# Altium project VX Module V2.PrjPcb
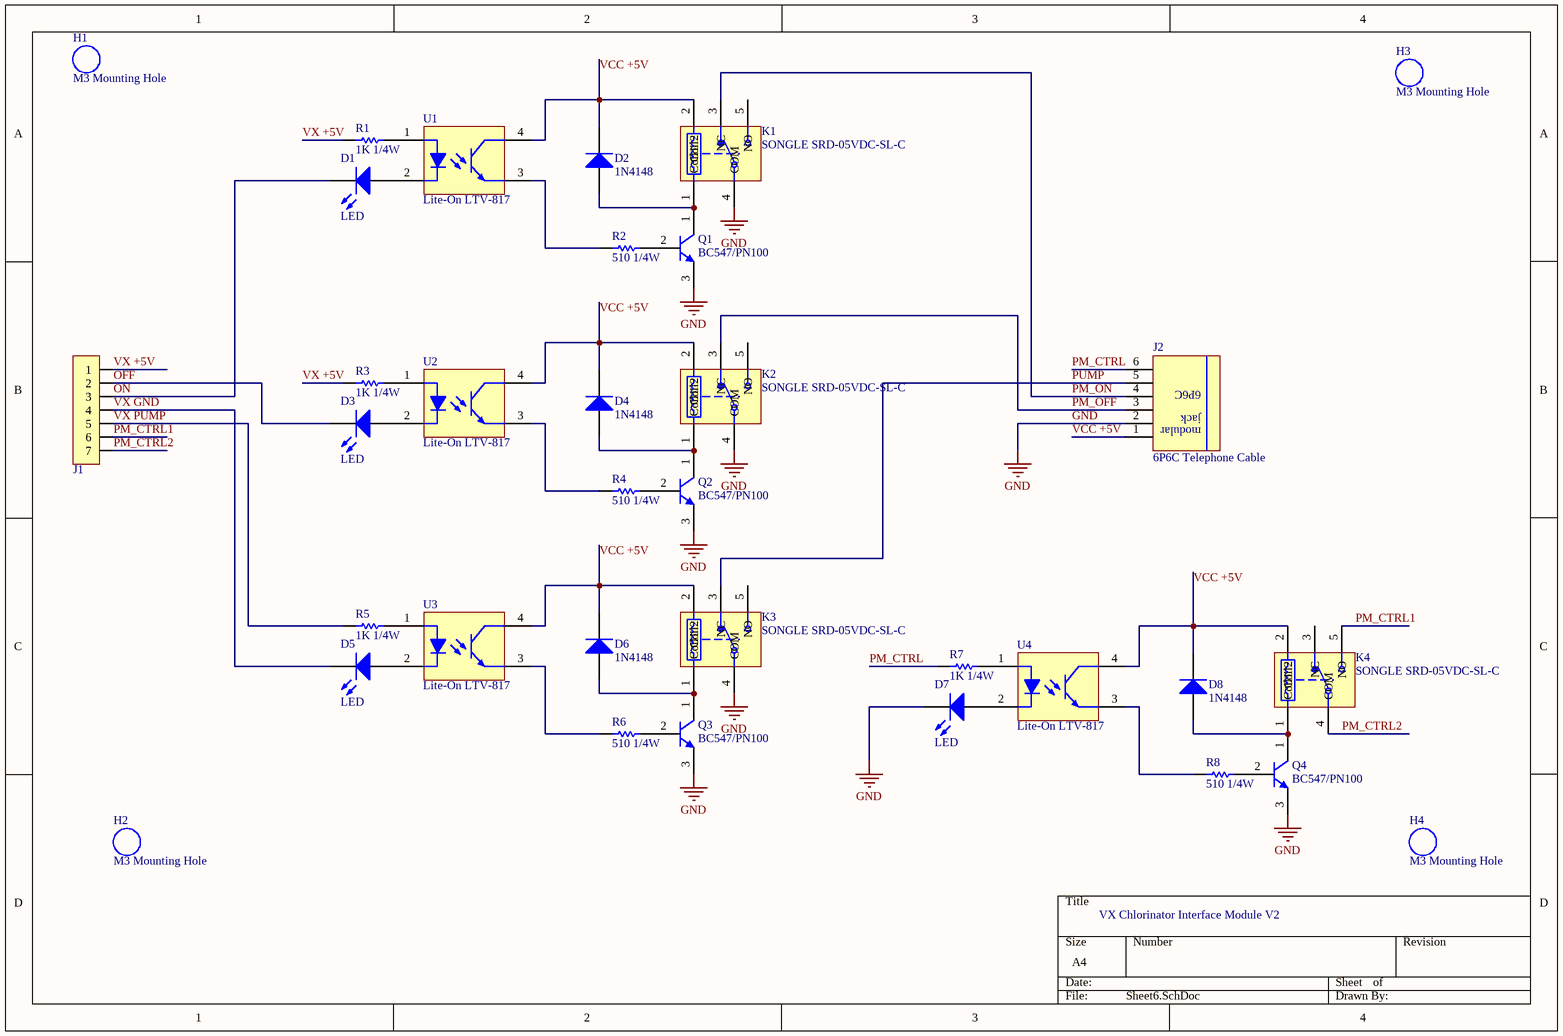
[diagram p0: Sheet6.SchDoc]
1 sheet, 34 parts. Net scope: global (net labels, ports and power ports of the same name join across sheets).

## Sheet Sheet6.SchDoc
size A4

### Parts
D1  LED  [PCB-6hmn14p3euwrtpae4j9f-1]
D2  1N4148  [PCB-rs5tsfd40ie4dftnk2d5-1]
D3  LED  [PCB-6hmn14p3euwrtpae4j9f-1]
D4  1N4148  [PCB-rs5tsfd40ie4dftnk2d5-1]
D5  LED  [PCB-6hmn14p3euwrtpae4j9f-1]
D6  1N4148  [PCB-rs5tsfd40ie4dftnk2d5-1]
D7  LED  [PCB-6hmn14p3euwrtpae4j9f-1]
D8  1N4148  [PCB-rs5tsfd40ie4dftnk2d5-1]
H1  M3 Mounting Hole  [PCB-sb9r54v1ukudlsmquqqd-1]
H2  M3 Mounting Hole  [PCB-sb9r54v1ukudlsmquqqd-1]
H3  M3 Mounting Hole  [PCB-sb9r54v1ukudlsmquqqd-1]
H4  M3 Mounting Hole  [PCB-sb9r54v1ukudlsmquqqd-1]
J1  7pin header  [PCBComponent_1 - duplicate]  (value not drawn)
J2  6P6C Telephone Cable  [PCB-617631-1]
K1  SONGLE SRD-05VDC-SL-C  [PCB-g2fdo3sb6id1q29ao90z-1]
K2  SONGLE SRD-05VDC-SL-C  [PCB-g2fdo3sb6id1q29ao90z-1]
K3  SONGLE SRD-05VDC-SL-C  [PCB-g2fdo3sb6id1q29ao90z-1]
K4  SONGLE SRD-05VDC-SL-C  [PCB-g2fdo3sb6id1q29ao90z-1]
Q1  BC547/PN100  [ONSC-TO-92-3-29-11_AM_BL]
Q2  BC547/PN100  [ONSC-TO-92-3-29-11_AM_BL]
Q3  BC547/PN100  [ONSC-TO-92-3-29-11_AM_BL]
Q4  BC547/PN100  [ONSC-TO-92-3-29-11_AM_BL]
R1  1K 1/4W  [PCB-b0svi7yxgb64se8nuirk-1]
R2  510 1/4W  [PCB-b0svi7yxgb64se8nuirk-1]
R3  1K 1/4W  [PCB-b0svi7yxgb64se8nuirk-1]
R4  510 1/4W  [PCB-b0svi7yxgb64se8nuirk-1]
R5  1K 1/4W  [PCB-b0svi7yxgb64se8nuirk-1]
R6  510 1/4W  [PCB-b0svi7yxgb64se8nuirk-1]
R7  1K 1/4W  [PCB-b0svi7yxgb64se8nuirk-1]
R8  510 1/4W  [PCB-b0svi7yxgb64se8nuirk-1]
U1  Lite-On LTV-817  [PCBComponent_1 - duplicate]
U2  Lite-On LTV-817  [PCBComponent_1 - duplicate]
U3  Lite-On LTV-817  [PCBComponent_1 - duplicate]
U4  Lite-On LTV-817  [PCBComponent_1 - duplicate]

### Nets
GND: D7.2(K) J2.2 K1.4(COM) K2.4(COM) K3.4(COM) Q1.3(E) Q2.3(E) Q3.3(E) Q4.3(E)
OFF: D3.2(K) J1.2
ON: D1.2(K) J1.3
PM_CTRL: J2.6 R7.2
PM_CTRL1: J1.6 K4.5(NO)
PM_CTRL2: J1.7 K4.4(COM)
PM_OFF: J2.3 K2.3(NC)
PM_ON: J2.4 K1.3(NC)
PUMP: J2.5 K3.3(NC)
VCC +5V: D2.2(K) D4.2(K) D6.2(K) D8.2(K) J2.1 K1.2(Coil2) K2.2(Coil2) K3.2(Coil2) K4.2(Coil2) U1.4(C) U2.4(C) U3.4(C) U4.4(C)
VX +5V: J1.1 R1.2 R3.2
VX GND: D5.2(K) J1.4
VX PUMP: J1.5 R5.2
NetD1_1: D1.1(A) U1.2(C)
NetD2_1: D2.1(A) K1.1(Coil1) Q1.1(C)
NetD3_1: D3.1(A) U2.2(C)
NetD4_1: D4.1(A) K2.1(Coil1) Q2.1(C)
NetD5_1: D5.1(A) U3.2(C)
NetD6_1: D6.1(A) K3.1(Coil1) Q3.1(C)
NetD7_1: D7.1(A) U4.2(C)
NetD8_1: D8.1(A) K4.1(Coil1) Q4.1(C)
NetQ1_2: Q1.2(B) R2.2
NetQ2_2: Q2.2(B) R4.2
NetQ3_2: Q3.2(B) R6.2
NetQ4_2: Q4.2(B) R8.2
NetR1_1: R1.1 U1.1(A)
NetR2_1: R2.1 U1.3(E)
NetR3_1: R3.1 U2.1(A)
NetR4_1: R4.1 U2.3(E)
NetR5_1: R5.1 U3.1(A)
NetR6_1: R6.1 U3.3(E)
NetR7_1: R7.1 U4.1(A)
NetR8_1: R8.1 U4.3(E)

Not connected (* = marked no-connect by the designer): K1 5(NO); K2 5(NO); K3 5(NO); K4 3(NC)

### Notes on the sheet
- VX Chlorinator Interface Module V2

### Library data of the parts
D1 D3 D5 D7 = CMP-9d1f5758637d42d8-1: TLHR5205 Red LED, 625 nm 5mm (T-1 3/4), Round Lens Through Hole package; Peak Wavelength: 635 nm; Wavelength: 625 nm; Lead-Free Status: Lead Free; Luminous Intensity: 70.0 mcd; Viewing Angle: 14 °; Lead Length: 24.0 mm; Voltage Rating (DC): 2.00 V
D2 D4 D6 D8 = CMP-814702-5: DIODE GEN PURP 100V 200MA DO35; Manufacturer: Fairchild Semiconductor; Forward Voltage: 1.0 V; Capacitance: 4e-12 F; Lead-Free Status: Lead Free; Polarity: Standard; Voltage Rating (DC): 100.0 V
H1-H4 = CMP-2eajnev4pcr11g3c6yc7-1: M3 Mountig Hole
J1 = CMP-b84c7047322f678b-1: Conn Unshrouded Header HDR 7 POS 2.54mm Solder ST Thru-Hole Bag
J2 = CMP-617631-5: CONN MOD JACK R/A 6P6C; Contact Resistance: 0.02 ?; Current Rating: 1.5 A; Gender: Male; Insulation Resistance: 500000000.0 ?; Number of Contacts: 6; Number of Mating Cycles: 500
K1-K4 = CMP-t5gqq9hbd8q2y5oaholr-2: SONGLE SRD-05VDC-SL-C SPDT 5Volt Relay
Q1-Q4 = CMP-860851-2: Amplifier Transistor, NPN Silicon, 3-Pin TO-92, Pb-Free, Ammo Box; Current Rating: 0.1 A; Lead-Free Status: Lead Free; Power Dissipation: 0.625 W; Voltage Rating (DC): 45.0 V
R1-R8 = CMP-b3d47a8ce28e6c13-3: Resistor; Metal Film; Res 1 Kilohms; Pwr-Rtg 0.25 W; Tol 0.1%; Axial; TCR 15 ppm/DegC; Manufacturer Part Number: YR1B1K0CC; Temperature Coefficient: -15.0 ppm/°C to 15.0 ppm/°C; Lead Length: 25.0 mm; Voltage Rating (DC): 500 V; ELV Compliant: Compliant
U1-U4 = CMP-1524854-5: LTV Series Single Channel 35 V 5000 Vrms Transistor Output Optocoupler - DIP-4; Number of Channels: 1; Lead-Free Status: Lead Free; Input Voltage (DC): 1.20 V; Output Voltage: 35.0 V (max); Rise Time: 4.00 µs; Isolation Voltage: 5.00 kV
